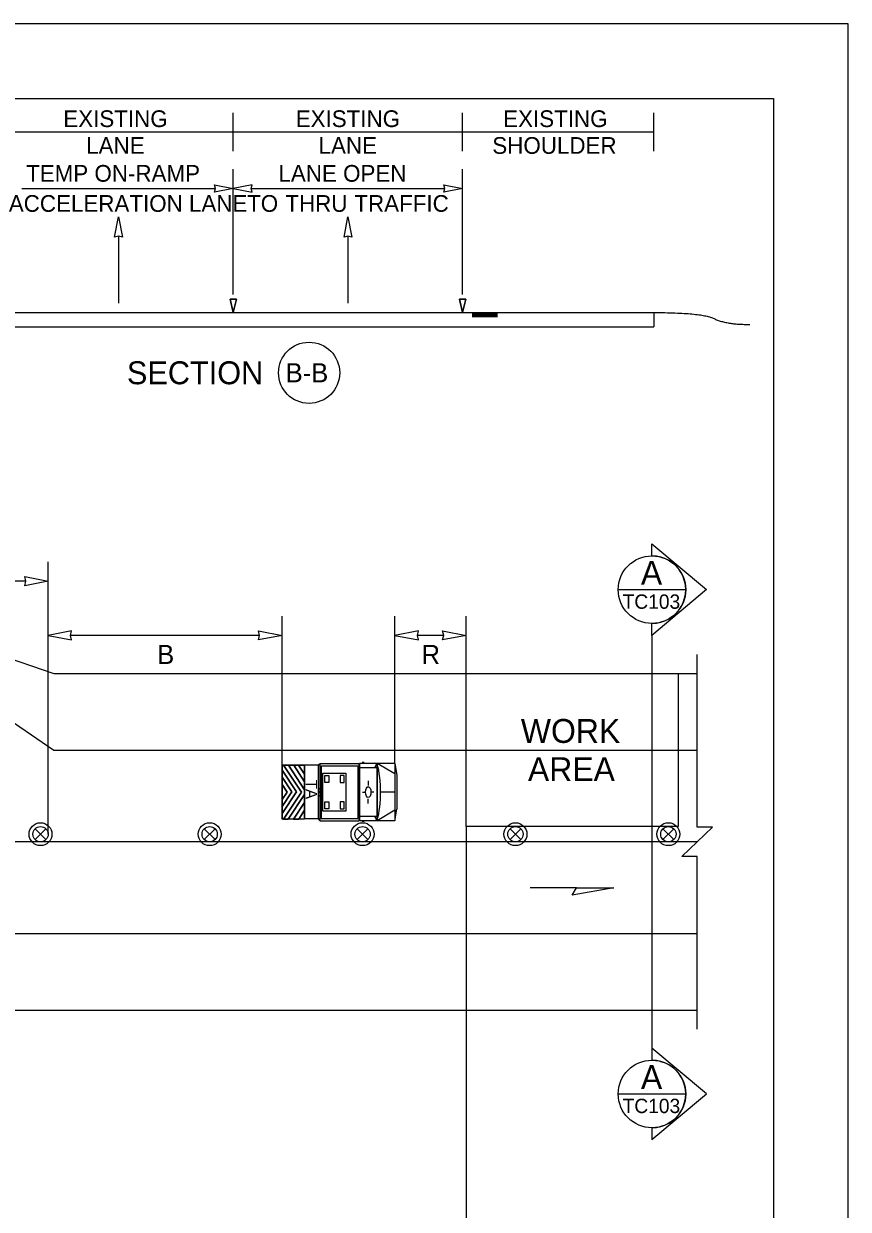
# Model space of a CAD drawing. Extents: x 99999 to 100116, y 99995 to 100013.
# Drawn here: x 100072.611 to 100076.062, y 100005.726 to 100010.687 of the extents above; entities that cross this region are included whole.
import ezdxf

# ---------------------------------------------------------------- set-up
doc = ezdxf.new("R2010")
doc.units = 0
for name, color, linetype in [('RD_MK_LineEdgeYellow', 7, 'Continuous'), ('RD_MK_LineLane', 7, 'Continuous'), ('SH_GI_PlotLimits', 7, 'Continuous'), ('SH_GI_SheetBorder', 7, 'Continuous'), ('SH_TI_WZSectionCut', 7, 'Continuous'), ('TR_WZ_ArrowLeftStrRightTurn', 7, 'Continuous'), ('TR_WZ_TrafficSafetyDrum', 7, 'Continuous'), ('TR_WZ_TransportableAttenuator', 7, 'Continuous'), ('TR_WZ_WorkAreaLabel', 7, 'Continuous'), ('TR_WZ_WorkZoneDetails', 7, 'Continuous'), ('TR_WZ_WorkZoneTextCurrent', 7, 'Continuous')]:
    doc.layers.add(name, color=color, linetype=linetype)

msp = doc.modelspace()

# ---------------------------------------------------------------- linework, layer by layer
at = {"layer": 'RD_MK_LineEdgeYellow'}
for p, q in [((100072.1758, 100008.032), (100072.7368, 100007.648)), ((100072.7368, 100007.648), (100075.43, 100007.648)), ((100068.195, 100006.88), (100075.43, 100006.88))]:
    msp.add_line(p, q, dxfattribs=at)
at = {"layer": 'RD_MK_LineLane'}
msp.add_lwpolyline([(100075.43, 100007.264), (100068.195, 100007.264)], dxfattribs=at)
at = {"layer": 'SH_GI_PlotLimits'}
msp.add_lwpolyline([(100059.0625, 99999.6875), (100076.0625, 99999.6875), (100076.0625, 100010.6875), (100059.0625, 100010.6875)], close=True, dxfattribs=at)
at = {"layer": 'SH_GI_SheetBorder'}
for p, q in [((100060, 100010.375), (100075.75, 100010.375)), ((100075.75, 100010.375), (100075.75, 100000))]:
    msp.add_line(p, q, dxfattribs=at)
at = {"layer": 'SH_TI_WZSectionCut'}
for p, q in [((100075.2407, 100008.4604), (100075.2407, 100008.5103)), ((100075.2407, 100008.5103), (100075.4688, 100008.3192)), ((100075.4688, 100008.3192), (100075.2407, 100008.128)), ((100075.2407, 100008.128), (100075.2407, 100008.1779)), ((100075.2407, 100008.128), (100075.2407, 100006.4)), ((100075.2407, 100006.4), (100075.2407, 100006.3501)), ((100075.4689, 100006.2089), (100075.2407, 100006.4)), ((100075.2407, 100006.0178), (100075.4689, 100006.2089)), ((100075.2407, 100006.0677), (100075.2407, 100006.0178))]:
    msp.add_line(p, q, dxfattribs=at)
for points in [[(100075.0995, 100008.3192), (100075.3819, 100008.3192)], [(100075.0995, 100006.2089), (100075.3819, 100006.2089)]]:
    msp.add_lwpolyline(points, dxfattribs=at)
for centre in [(100075.2407, 100008.3192), (100075.2407, 100006.2089)]:
    msp.add_circle(centre, 0.1412, dxfattribs=at)
for centre in [(100075.2407, 100008.3192), (100075.2407, 100006.2089)]:
    msp.add_arc(centre, 0.1412, 269.9978, 90.0022, dxfattribs=at)
at = {"layer": 'TR_WZ_ArrowLeftStrRightTurn'}
for p, q in [((100073.0083, 100009.7986), (100073.0083, 100009.5187)), ((100073.9683, 100009.7986), (100073.9683, 100009.5187))]:
    msp.add_line(p, q, dxfattribs=at)
for points in [[(100073.0083, 100009.8787), (100073.0248, 100009.7947), (100073.0083, 100009.7986), (100072.9918, 100009.7947)], [(100073.9683, 100009.8787), (100073.9848, 100009.7947), (100073.9683, 100009.7986), (100073.9518, 100009.7947)]]:
    msp.add_lwpolyline(points, close=True, dxfattribs=at)
at = {"layer": 'TR_WZ_TrafficSafetyDrum'}
for p, q in [((100072.6589, 100007.2734), (100072.7042, 100007.3186)), ((100072.7042, 100007.2734), (100072.6589, 100007.3186)), ((100073.3668, 100007.2734), (100073.412, 100007.3186)), ((100073.412, 100007.2734), (100073.3668, 100007.3186)), ((100074.0068, 100007.2734), (100074.052, 100007.3186)), ((100074.052, 100007.2734), (100074.0068, 100007.3186)), ((100074.6468, 100007.2734), (100074.692, 100007.3186)), ((100074.692, 100007.2734), (100074.6468, 100007.3186)), ((100075.2868, 100007.2734), (100075.332, 100007.3186)), ((100075.332, 100007.2734), (100075.2868, 100007.3186))]:
    msp.add_line(p, q, dxfattribs=at)
for centre, radius in [((100072.6815, 100007.296), 0.048), ((100072.6815, 100007.296), 0.048), ((100073.3894, 100007.296), 0.048), ((100073.3894, 100007.296), 0.048), ((100074.0294, 100007.296), 0.048), ((100074.0294, 100007.296), 0.048), ((100074.6694, 100007.296), 0.048), ((100074.6694, 100007.296), 0.048), ((100075.3094, 100007.296), 0.048), ((100075.3094, 100007.296), 0.048), ((100072.6815, 100007.296), 0.032), ((100073.3894, 100007.296), 0.032), ((100074.0294, 100007.296), 0.032), ((100074.6694, 100007.296), 0.032), ((100075.3094, 100007.296), 0.032)]:
    msp.add_circle(centre, radius, dxfattribs=at)
at = {"layer": 'TR_WZ_TransportableAttenuator'}
for p, q in [((100073.7735, 100007.4722), (100073.6986, 100007.5849)), ((100073.6986, 100007.5849), (100073.719, 100007.5849)), ((100073.6986, 100007.5849), (100073.7735, 100007.4722)), ((100073.719, 100007.5849), (100073.6986, 100007.5849)), ((100073.719, 100007.5849), (100073.7868, 100007.4822)), ((100073.7868, 100007.4822), (100073.719, 100007.5849)), ((100073.7868, 100007.5154), (100073.7412, 100007.5849)), ((100073.7412, 100007.5849), (100073.7615, 100007.5849)), ((100073.7615, 100007.5849), (100073.7412, 100007.5849)), ((100073.7412, 100007.5849), (100073.7868, 100007.5154)), ((100073.7615, 100007.5849), (100073.7868, 100007.5467)), ((100073.7868, 100007.5467), (100073.7615, 100007.5849)), ((100073.7868, 100007.3596), (100073.7868, 100007.5849)), ((100073.8512, 100007.5849), (100073.7868, 100007.5849)), ((100073.8436, 100007.5808), (100073.8436, 100007.3633)), ((100073.8471, 100007.5881), (100073.8506, 100007.5881)), ((100073.8506, 100007.5881), (100073.8506, 100007.3559)), ((100073.8512, 100007.592), (100074.0137, 100007.592)), ((100073.8512, 100007.592), (100073.8512, 100007.352)), ((100073.8512, 100007.5845), (100073.8512, 100007.3596)), ((100073.8558, 100007.5825), (100073.8558, 100007.3616)), ((100073.8558, 100007.5825), (100074.0091, 100007.5825)), ((100074.0091, 100007.5825), (100074.0091, 100007.3616)), ((100074.0137, 100007.592), (100074.0137, 100007.352)), ((100074.0159, 100007.592), (100074.0159, 100007.352)), ((100074.1651, 100007.592), (100074.0159, 100007.592)), ((100074.0362, 100007.5954), (100074.0273, 100007.5954)), ((100074.0891, 100007.592), (100074.0796, 100007.5734)), ((100074.0891, 100007.592), (100074.0891, 100007.352)), ((100074.0905, 100007.592), (100074.0905, 100007.352)), ((100074.1651, 100007.5481), (100074.0905, 100007.592)), ((100074.1651, 100007.592), (100074.1651, 100007.352)), ((100074.1651, 100007.592), (100074.1724, 100007.5436)), ((100073.6924, 100007.5635), (100073.7525, 100007.4729)), ((100073.6924, 100007.5343), (100073.6924, 100007.5635)), ((100073.7525, 100007.4729), (100073.6924, 100007.5635)), ((100073.6924, 100007.5635), (100073.6924, 100007.5343)), ((100073.7332, 100007.4732), (100073.6924, 100007.5343)), ((100073.6924, 100007.5343), (100073.7332, 100007.4732)), ((100073.7868, 100007.5467), (100073.7868, 100007.5154)), ((100073.7868, 100007.5154), (100073.7868, 100007.5467)), ((100074.0891, 100007.5734), (100074.0159, 100007.5734)), ((100074.1724, 100007.5436), (100074.1724, 100007.4005)), ((100073.6924, 100007.5034), (100073.7133, 100007.4724)), ((100073.6924, 100007.441), (100073.6924, 100007.5034)), ((100073.7133, 100007.4724), (100073.6924, 100007.5034)), ((100073.6924, 100007.5034), (100073.6924, 100007.441)), ((100073.7868, 100007.4822), (100073.7868, 100007.4621)), ((100073.7868, 100007.4621), (100073.7868, 100007.4822)), ((100073.8436, 100007.4889), (100073.8506, 100007.4844)), ((100074.0533, 100007.5196), (100074.0533, 100007.5002)), ((100073.6924, 100007.4118), (100073.7332, 100007.4732)), ((100073.7332, 100007.4732), (100073.6924, 100007.4118)), ((100073.7525, 100007.4729), (100073.6924, 100007.3824)), ((100073.6924, 100007.3824), (100073.7525, 100007.4729)), ((100073.7133, 100007.4724), (100073.6924, 100007.441)), ((100073.6924, 100007.441), (100073.7133, 100007.4724)), ((100073.6986, 100007.3594), (100073.7735, 100007.4722)), ((100073.7735, 100007.4722), (100073.6986, 100007.3594)), ((100073.7868, 100007.4621), (100073.7186, 100007.3594)), ((100073.7186, 100007.3594), (100073.7868, 100007.4621)), ((100073.8436, 100007.4551), (100073.8506, 100007.4596)), ((100073.8455, 100007.472), (100073.8487, 100007.472)), ((100073.8471, 100007.4754), (100073.8471, 100007.4686)), ((100074.0295, 100007.4722), (100074.0394, 100007.4721)), ((100074.0422, 100007.4716), (100074.0422, 100007.4716)), ((100074.0533, 100007.4245), (100074.0533, 100007.4438)), ((100074.0771, 100007.4722), (100074.0672, 100007.4721)), ((100074.1651, 100007.472), (100074.1051, 100007.472)), ((100073.6924, 100007.3824), (100073.6924, 100007.4118)), ((100073.6924, 100007.4118), (100073.6924, 100007.3824)), ((100073.7406, 100007.3594), (100073.7868, 100007.4289)), ((100073.7868, 100007.4289), (100073.7406, 100007.3594)), ((100073.7868, 100007.3958), (100073.7622, 100007.3594)), ((100073.7622, 100007.3594), (100073.7868, 100007.3958)), ((100073.7868, 100007.4289), (100073.7868, 100007.3958)), ((100073.7868, 100007.3958), (100073.7868, 100007.4289)), ((100074.1651, 100007.3959), (100074.0905, 100007.352)), ((100074.1651, 100007.352), (100074.1724, 100007.4005)), ((100073.7186, 100007.3594), (100073.6986, 100007.3594)), ((100073.6986, 100007.3594), (100073.7186, 100007.3594)), ((100073.7622, 100007.3594), (100073.7406, 100007.3594)), ((100073.7406, 100007.3594), (100073.7622, 100007.3594)), ((100073.8512, 100007.3596), (100073.7868, 100007.3596)), ((100073.8471, 100007.3559), (100073.8506, 100007.3559)), ((100073.8512, 100007.352), (100074.0137, 100007.352)), ((100073.8558, 100007.3616), (100074.0091, 100007.3616)), ((100074.0891, 100007.3706), (100074.0159, 100007.3706)), ((100074.1651, 100007.352), (100074.0159, 100007.352)), ((100074.0362, 100007.3487), (100074.0273, 100007.3487)), ((100074.0813, 100007.3706), (100074.0891, 100007.352))]:
    msp.add_line(p, q, dxfattribs=at)
for points in [[(100073.7868, 100007.3594), (100073.6924, 100007.3594), (100073.6924, 100007.5849), (100073.7868, 100007.5849)], [(100073.8638, 100007.552), (100073.9598, 100007.552), (100073.9598, 100007.392), (100073.8638, 100007.392)], [(100073.8718, 100007.542), (100073.8878, 100007.542), (100073.8878, 100007.512), (100073.8718, 100007.512)], [(100073.9518, 100007.542), (100073.9358, 100007.542), (100073.9358, 100007.512), (100073.9518, 100007.512)], [(100073.8718, 100007.432), (100073.8878, 100007.432), (100073.8878, 100007.402), (100073.8718, 100007.402)], [(100073.9518, 100007.432), (100073.9358, 100007.432), (100073.9358, 100007.402), (100073.9518, 100007.402)]]:
    msp.add_lwpolyline(points, close=True, dxfattribs=at)
msp.add_lwpolyline([(100073.7868, 100007.5849), (100073.6924, 100007.5849), (100073.6924, 100007.3594), (100073.7868, 100007.3596)], dxfattribs=at)
for centre, major_axis, start_param, end_param in [((100073.8471, 100007.5807), (0, 0.00732), 6.283185, 7.853982), ((100073.9838, 100007.472), (0, 0.2519), 4.215852, 5.209111), ((100073.8471, 100007.3633), (0, -0.00732), 4.712389, 6.283185)]:
    msp.add_ellipse(centre, major_axis=major_axis, ratio=0.481608, start_param=start_param, end_param=end_param, dxfattribs=at)
for centre, major_axis in [((100074.0533, 100007.472), (0, -0.0231)), ((100073.8471, 100007.472), (0, -0.00338))]:
    msp.add_ellipse(centre, major_axis=major_axis, ratio=0.481608, dxfattribs=at)
at = {"layer": 'TR_WZ_WorkZoneDetails'}
for p, q in [((100073.4883, 100010.154), (100073.4883, 100010.314)), ((100074.4483, 100010.154), (100074.4483, 100010.314)), ((100075.2483, 100010.154), (100075.2483, 100010.314)), ((100073.4883, 100010.234), (100072.5283, 100010.234)), ((100074.4483, 100010.234), (100073.4883, 100010.234)), ((100075.2483, 100010.234), (100074.4483, 100010.234)), ((100073.4883, 100009.5546), (100073.4883, 100010.0783)), ((100074.4483, 100009.5546), (100074.4483, 100010.0783)), ((100072.6033, 100009.9983), (100073.4133, 100009.9983)), ((100073.5633, 100009.9983), (100074.3733, 100009.9983)), ((100070.7683, 100009.4787), (100075.2483, 100009.4787)), ((100074.5947, 100009.4746), (100074.4883, 100009.4746)), ((100074.5947, 100009.4701), (100074.4883, 100009.4701)), ((100074.5947, 100009.4655), (100074.4883, 100009.4655)), ((100075.2483, 100009.4787), (100075.2483, 100009.4187)), ((100070.7683, 100009.4187), (100075.2483, 100009.4187)), ((100074.5947, 100009.4614), (100074.4883, 100009.4614)), ((100072.7135, 100007.296), (100072.7135, 100008.435)), ((100072.6198, 100008.355), (100072.2056, 100008.355)), ((100073.6924, 100007.5849), (100073.6924, 100008.208)), ((100074.1651, 100007.592), (100074.1651, 100008.208)), ((100074.4628, 100007.968), (100074.4628, 100008.208)), ((100072.1758, 100008.16), (100072.7368, 100007.968)), ((100073.5987, 100008.128), (100072.8072, 100008.128)), ((100074.3691, 100008.128), (100074.2588, 100008.128)), ((100072.7368, 100007.968), (100075.43, 100007.968)), ((100074.4628, 100007.328), (100074.4628, 100005.4763)), ((100074.9242, 100007.072), (100074.7313, 100007.072)), ((100068.195, 100006.56), (100075.43, 100006.56))]:
    msp.add_line(p, q, dxfattribs=at)
for points in [[(100073.4883, 100009.9983), (100073.4097, 100009.9829), (100073.4133, 100009.9983), (100073.4097, 100010.0137)], [(100073.4883, 100009.9983), (100073.5669, 100009.9829), (100073.5633, 100009.9983), (100073.5669, 100010.0137)], [(100074.4483, 100009.9983), (100074.3697, 100009.9829), (100074.3733, 100009.9983), (100074.3697, 100010.0137)], [(100073.4883, 100009.4787), (100073.5017, 100009.5346), (100073.475, 100009.5346)], [(100074.4483, 100009.4787), (100074.4617, 100009.5346), (100074.435, 100009.5346)], [(100072.7135, 100008.355), (100072.6152, 100008.3358), (100072.6198, 100008.355), (100072.6152, 100008.3743)], [(100072.7135, 100008.128), (100072.8118, 100008.1088), (100072.8072, 100008.128), (100072.8118, 100008.1473)], [(100073.6924, 100008.128), (100073.5941, 100008.1088), (100073.5987, 100008.128), (100073.5941, 100008.1473)], [(100074.1651, 100008.128), (100074.2634, 100008.1088), (100074.2588, 100008.128), (100074.2634, 100008.1473)], [(100074.4628, 100008.128), (100074.3645, 100008.1088), (100074.3691, 100008.128), (100074.3645, 100008.1473)], [(100074.4628, 100007.328), (100074.4628, 100007.968), (100075.35, 100007.968), (100075.35, 100007.328)], [(100075.0815, 100007.072), (100074.9064, 100007.0412), (100074.9242, 100007.072)]]:
    msp.add_lwpolyline(points, close=True, dxfattribs=at)
for points in [[(100073.475, 100009.5346), (100073.5017, 100009.5346), (100073.4883, 100009.4787), (100073.475, 100009.5346)], [(100074.435, 100009.5346), (100074.4617, 100009.5346), (100074.4483, 100009.4787), (100074.435, 100009.5346)], [(100075.43, 100006.48), (100075.43, 100007.2021), (100075.366, 100007.2021), (100075.494, 100007.326), (100075.43, 100007.326), (100075.43, 100008.048)]]:
    msp.add_lwpolyline(points, dxfattribs=at)
msp.add_circle((100073.8056, 100009.2268), 0.128, dxfattribs=at)
msp.add_open_spline([(100075.2483, 100009.4787), (100075.4493, 100009.4787), (100075.5496, 100009.429), (100075.65, 100009.429)], degree=2, dxfattribs=at)

# ---------------------------------------------------------------- texts
at = {"layer": 'SH_TI_WZSectionCut'}
for s, height, rotation, p in [('A', 0.1, 0.01, (100075.1945, 100008.3398)), ('TC103', 0.06, 360, (100075.118, 100008.2392)), ('A', 0.1, 0.01, (100075.1945, 100006.2295)), ('TC103', 0.06, 360, (100075.118, 100006.1289))]:
    msp.add_text(s, height=height, rotation=rotation, dxfattribs=at).set_placement(p)
at = {"layer": 'TR_WZ_TransportableAttenuator'}
msp.add_text('TA', height=0.048, rotation=270, dxfattribs=at).set_placement((100073.7912, 100007.5246))
at = {"layer": 'TR_WZ_WorkAreaLabel'}
for s, p in [('WORK', (100074.6919, 100007.678)), ('AREA', (100074.7215, 100007.518))]:
    msp.add_text(s, height=0.1, dxfattribs=at).set_placement(p)
at = {"layer": 'TR_WZ_WorkZoneDetails'}
for s, p in [('EXISTING', (100072.7768, 100010.255)), ('EXISTING', (100073.7495, 100010.255)), ('EXISTING', (100074.6179, 100010.255)), ('LANE', (100072.8725, 100010.143)), ('LANE', (100073.8453, 100010.143)), ('SHOULDER', (100074.5725, 100010.143)), ('TEMP ON-RAMP', (100072.6211, 100010.0263)), ('LANE OPEN', (100073.6774, 100010.0263)), ('ACCELERATION LANE', (100072.5487, 100009.9003)), ('TO', (100073.5461, 100009.9003)), ('THRU', (100073.7062, 100009.9003)), ('TRAFFIC', (100073.995, 100009.9003))]:
    msp.add_text(s, height=0.07, dxfattribs=at).set_placement(p)
for s, height, p in [('SECTION', 0.096, (100073.0431, 100009.1788)), ('B-B', 0.08, (100073.7075, 100009.1868))]:
    msp.add_text(s, height=height, rotation=360, dxfattribs=at).set_placement(p)
at = {"layer": 'TR_WZ_WorkZoneTextCurrent'}
for s, p in [('B', (100073.1698, 100008.008)), ('R', (100074.2764, 100008.008))]:
    msp.add_text(s, height=0.08, dxfattribs=at).set_placement(p)

doc.saveas('drawing.dxf')
